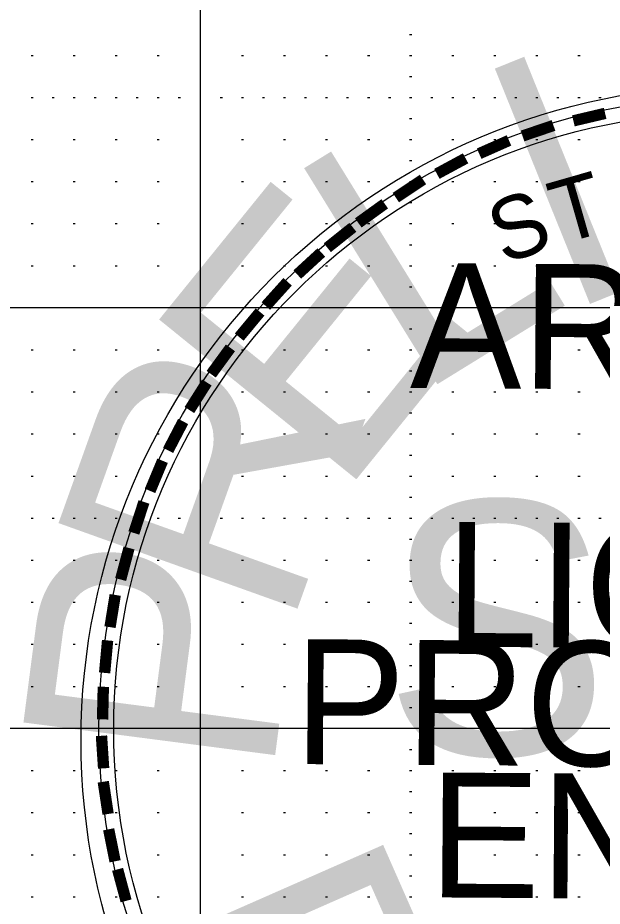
# Model space of a CAD drawing. Extents: x -1.6 to 32.4, y -1.9 to 21.6.
# Drawn here: x 27.374 to 28.763, y 17.122 to 19.234 of the extents above; entities that cross this region are included whole.
import ezdxf

# ---------------------------------------------------------------- set-up
doc = ezdxf.new("R2010")
doc.units = 0
for name, color, linetype in [('Level 4', 7, 'Continuous'), ('Level 49', 7, 'Continuous'), ('Level 5', 7, 'Continuous'), ('R_Border Prelim', 7, 'Continuous'), ('Stamp Mask', 7, 'Continuous')]:
    doc.layers.add(name, color=color, linetype=linetype)

msp = doc.modelspace()

# ---------------------------------------------------------------- linework, layer by layer
at = {"layer": 'Level 4'}
for p, q in [((27.808, 0.545), (27.808, 19.7217)), ((31.617, 18.545), (-0.001, 18.545)), ((31.617, 17.545), (-0.001, 17.545))]:
    msp.add_line(p, q, dxfattribs=at)
at = {"layer": 'Level 5'}
for p, q in [((28.3055, 19.195), (28.3105, 19.195)), ((27.4055, 19.145), (27.4105, 19.145)), ((27.5055, 19.145), (27.5105, 19.145)), ((27.6055, 19.145), (27.6105, 19.145)), ((27.7055, 19.145), (27.7105, 19.145)), ((27.9055, 19.145), (27.9105, 19.145)), ((28.0055, 19.145), (28.0105, 19.145)), ((28.1055, 19.145), (28.1105, 19.145)), ((28.2055, 19.145), (28.2105, 19.145)), ((28.3055, 19.145), (28.3105, 19.145)), ((28.4055, 19.145), (28.4105, 19.145)), ((28.5055, 19.145), (28.5105, 19.145)), ((28.6055, 19.145), (28.6105, 19.145)), ((28.7055, 19.145), (28.7105, 19.145)), ((28.3055, 19.095), (28.3105, 19.095)), ((27.4055, 19.045), (27.4105, 19.045)), ((27.4555, 19.045), (27.4605, 19.045)), ((27.5055, 19.045), (27.5105, 19.045)), ((27.5555, 19.045), (27.5605, 19.045)), ((27.6055, 19.045), (27.6105, 19.045)), ((27.6555, 19.045), (27.6605, 19.045)), ((27.7055, 19.045), (27.7105, 19.045)), ((27.7555, 19.045), (27.7605, 19.045)), ((27.8555, 19.045), (27.8605, 19.045)), ((27.9055, 19.045), (27.9105, 19.045)), ((27.9555, 19.045), (27.9605, 19.045)), ((28.0055, 19.045), (28.0105, 19.045)), ((28.0555, 19.045), (28.0605, 19.045)), ((28.1055, 19.045), (28.1105, 19.045)), ((28.1555, 19.045), (28.1605, 19.045)), ((28.2055, 19.045), (28.2105, 19.045)), ((28.2555, 19.045), (28.2605, 19.045)), ((28.3055, 19.045), (28.3105, 19.045)), ((28.3555, 19.045), (28.3605, 19.045)), ((28.4055, 19.045), (28.4105, 19.045)), ((28.4555, 19.045), (28.4605, 19.045)), ((28.5055, 19.045), (28.5105, 19.045)), ((28.5555, 19.045), (28.5605, 19.045)), ((28.6055, 19.045), (28.6105, 19.045)), ((28.6555, 19.045), (28.6605, 19.045)), ((28.7055, 19.045), (28.7105, 19.045)), ((28.7555, 19.045), (28.7605, 19.045)), ((28.3055, 18.995), (28.3105, 18.995)), ((27.4055, 18.945), (27.4105, 18.945)), ((27.5055, 18.945), (27.5105, 18.945)), ((27.6055, 18.945), (27.6105, 18.945)), ((27.7055, 18.945), (27.7105, 18.945)), ((27.9055, 18.945), (27.9105, 18.945)), ((28.0055, 18.945), (28.0105, 18.945)), ((28.1055, 18.945), (28.1105, 18.945)), ((28.2055, 18.945), (28.2105, 18.945)), ((28.3055, 18.945), (28.3105, 18.945)), ((28.4055, 18.945), (28.4105, 18.945)), ((28.5055, 18.945), (28.5105, 18.945)), ((28.6055, 18.945), (28.6105, 18.945)), ((28.7055, 18.945), (28.7105, 18.945)), ((28.3055, 18.895), (28.3105, 18.895)), ((27.4055, 18.845), (27.4105, 18.845)), ((27.5055, 18.845), (27.5105, 18.845)), ((27.6055, 18.845), (27.6105, 18.845)), ((27.7055, 18.845), (27.7105, 18.845)), ((27.9055, 18.845), (27.9105, 18.845)), ((28.0055, 18.845), (28.0105, 18.845)), ((28.1055, 18.845), (28.1105, 18.845)), ((28.2055, 18.845), (28.2105, 18.845)), ((28.3055, 18.845), (28.3105, 18.845)), ((28.4055, 18.845), (28.4105, 18.845)), ((28.5055, 18.845), (28.5105, 18.845)), ((28.6055, 18.845), (28.6105, 18.845)), ((28.7055, 18.845), (28.7105, 18.845)), ((28.3055, 18.795), (28.3105, 18.795)), ((27.4055, 18.745), (27.4105, 18.745)), ((27.5055, 18.745), (27.5105, 18.745)), ((27.6055, 18.745), (27.6105, 18.745)), ((27.7055, 18.745), (27.7105, 18.745)), ((27.9055, 18.745), (27.9105, 18.745)), ((28.0055, 18.745), (28.0105, 18.745)), ((28.1055, 18.745), (28.1105, 18.745)), ((28.2055, 18.745), (28.2105, 18.745)), ((28.3055, 18.745), (28.3105, 18.745)), ((28.4055, 18.745), (28.4105, 18.745)), ((28.5055, 18.745), (28.5105, 18.745)), ((28.6055, 18.745), (28.6105, 18.745)), ((28.7055, 18.745), (28.7105, 18.745)), ((28.3055, 18.695), (28.3105, 18.695)), ((27.4055, 18.645), (27.4105, 18.645)), ((27.5055, 18.645), (27.5105, 18.645)), ((27.6055, 18.645), (27.6105, 18.645)), ((27.7055, 18.645), (27.7105, 18.645)), ((27.9055, 18.645), (27.9105, 18.645)), ((28.0055, 18.645), (28.0105, 18.645)), ((28.1055, 18.645), (28.1105, 18.645)), ((28.2055, 18.645), (28.2105, 18.645)), ((28.3055, 18.645), (28.3105, 18.645)), ((28.4055, 18.645), (28.4105, 18.645)), ((28.5055, 18.645), (28.5105, 18.645)), ((28.6055, 18.645), (28.6105, 18.645)), ((28.7055, 18.645), (28.7105, 18.645)), ((28.3055, 18.595), (28.3105, 18.595)), ((28.3055, 18.495), (28.3105, 18.495)), ((27.4055, 18.445), (27.4105, 18.445)), ((27.5055, 18.445), (27.5105, 18.445)), ((27.6055, 18.445), (27.6105, 18.445)), ((27.7055, 18.445), (27.7105, 18.445)), ((27.9055, 18.445), (27.9105, 18.445)), ((28.0055, 18.445), (28.0105, 18.445)), ((28.1055, 18.445), (28.1105, 18.445)), ((28.2055, 18.445), (28.2105, 18.445)), ((28.3055, 18.445), (28.3105, 18.445)), ((28.4055, 18.445), (28.4105, 18.445)), ((28.5055, 18.445), (28.5105, 18.445)), ((28.6055, 18.445), (28.6105, 18.445)), ((28.7055, 18.445), (28.7105, 18.445)), ((28.3055, 18.395), (28.3105, 18.395)), ((27.4055, 18.345), (27.4105, 18.345)), ((27.5055, 18.345), (27.5105, 18.345)), ((27.6055, 18.345), (27.6105, 18.345)), ((27.7055, 18.345), (27.7105, 18.345)), ((27.9055, 18.345), (27.9105, 18.345)), ((28.0055, 18.345), (28.0105, 18.345)), ((28.1055, 18.345), (28.1105, 18.345)), ((28.2055, 18.345), (28.2105, 18.345)), ((28.3055, 18.345), (28.3105, 18.345)), ((28.4055, 18.345), (28.4105, 18.345)), ((28.5055, 18.345), (28.5105, 18.345)), ((28.6055, 18.345), (28.6105, 18.345)), ((28.7055, 18.345), (28.7105, 18.345)), ((28.3055, 18.295), (28.3105, 18.295)), ((27.4055, 18.245), (27.4105, 18.245)), ((27.5055, 18.245), (27.5105, 18.245)), ((27.6055, 18.245), (27.6105, 18.245)), ((27.7055, 18.245), (27.7105, 18.245)), ((27.9055, 18.245), (27.9105, 18.245)), ((28.0055, 18.245), (28.0105, 18.245)), ((28.1055, 18.245), (28.1105, 18.245)), ((28.2055, 18.245), (28.2105, 18.245)), ((28.3055, 18.245), (28.3105, 18.245)), ((28.4055, 18.245), (28.4105, 18.245)), ((28.5055, 18.245), (28.5105, 18.245)), ((28.6055, 18.245), (28.6105, 18.245)), ((28.7055, 18.245), (28.7105, 18.245)), ((28.3055, 18.195), (28.3105, 18.195)), ((27.4055, 18.145), (27.4105, 18.145)), ((27.5055, 18.145), (27.5105, 18.145)), ((27.6055, 18.145), (27.6105, 18.145)), ((27.7055, 18.145), (27.7105, 18.145)), ((27.9055, 18.145), (27.9105, 18.145)), ((28.0055, 18.145), (28.0105, 18.145)), ((28.1055, 18.145), (28.1105, 18.145)), ((28.2055, 18.145), (28.2105, 18.145)), ((28.3055, 18.145), (28.3105, 18.145)), ((28.4055, 18.145), (28.4105, 18.145)), ((28.5055, 18.145), (28.5105, 18.145)), ((28.6055, 18.145), (28.6105, 18.145)), ((28.7055, 18.145), (28.7105, 18.145)), ((28.3055, 18.095), (28.3105, 18.095)), ((27.4055, 18.045), (27.4105, 18.045)), ((27.4555, 18.045), (27.4605, 18.045)), ((27.5055, 18.045), (27.5105, 18.045)), ((27.5555, 18.045), (27.5605, 18.045)), ((27.6055, 18.045), (27.6105, 18.045)), ((27.6555, 18.045), (27.6605, 18.045)), ((27.7055, 18.045), (27.7105, 18.045)), ((27.7555, 18.045), (27.7605, 18.045)), ((27.8555, 18.045), (27.8605, 18.045)), ((27.9055, 18.045), (27.9105, 18.045)), ((27.9555, 18.045), (27.9605, 18.045)), ((28.0055, 18.045), (28.0105, 18.045)), ((28.0555, 18.045), (28.0605, 18.045)), ((28.1055, 18.045), (28.1105, 18.045)), ((28.1555, 18.045), (28.1605, 18.045)), ((28.2055, 18.045), (28.2105, 18.045)), ((28.2555, 18.045), (28.2605, 18.045)), ((28.3055, 18.045), (28.3105, 18.045)), ((28.3555, 18.045), (28.3605, 18.045)), ((28.4055, 18.045), (28.4105, 18.045)), ((28.4555, 18.045), (28.4605, 18.045)), ((28.5055, 18.045), (28.5105, 18.045)), ((28.5555, 18.045), (28.5605, 18.045)), ((28.6055, 18.045), (28.6105, 18.045)), ((28.6555, 18.045), (28.6605, 18.045)), ((28.7055, 18.045), (28.7105, 18.045)), ((28.7555, 18.045), (28.7605, 18.045)), ((28.3055, 17.995), (28.3105, 17.995)), ((27.4055, 17.945), (27.4105, 17.945)), ((27.5055, 17.945), (27.5105, 17.945)), ((27.6055, 17.945), (27.6105, 17.945)), ((27.7055, 17.945), (27.7105, 17.945)), ((27.9055, 17.945), (27.9105, 17.945)), ((28.0055, 17.945), (28.0105, 17.945)), ((28.1055, 17.945), (28.1105, 17.945)), ((28.2055, 17.945), (28.2105, 17.945)), ((28.3055, 17.945), (28.3105, 17.945)), ((28.4055, 17.945), (28.4105, 17.945)), ((28.5055, 17.945), (28.5105, 17.945)), ((28.6055, 17.945), (28.6105, 17.945)), ((28.7055, 17.945), (28.7105, 17.945)), ((28.3055, 17.895), (28.3105, 17.895)), ((27.4055, 17.845), (27.4105, 17.845)), ((27.5055, 17.845), (27.5105, 17.845)), ((27.6055, 17.845), (27.6105, 17.845)), ((27.7055, 17.845), (27.7105, 17.845)), ((27.9055, 17.845), (27.9105, 17.845)), ((28.0055, 17.845), (28.0105, 17.845)), ((28.1055, 17.845), (28.1105, 17.845)), ((28.2055, 17.845), (28.2105, 17.845)), ((28.3055, 17.845), (28.3105, 17.845)), ((28.4055, 17.845), (28.4105, 17.845)), ((28.5055, 17.845), (28.5105, 17.845)), ((28.6055, 17.845), (28.6105, 17.845)), ((28.7055, 17.845), (28.7105, 17.845)), ((28.3055, 17.795), (28.3105, 17.795)), ((27.4055, 17.745), (27.4105, 17.745)), ((27.5055, 17.745), (27.5105, 17.745)), ((27.6055, 17.745), (27.6105, 17.745)), ((27.7055, 17.745), (27.7105, 17.745)), ((27.9055, 17.745), (27.9105, 17.745)), ((28.0055, 17.745), (28.0105, 17.745)), ((28.1055, 17.745), (28.1105, 17.745)), ((28.2055, 17.745), (28.2105, 17.745)), ((28.3055, 17.745), (28.3105, 17.745)), ((28.4055, 17.745), (28.4105, 17.745)), ((28.5055, 17.745), (28.5105, 17.745)), ((28.6055, 17.745), (28.6105, 17.745)), ((28.7055, 17.745), (28.7105, 17.745)), ((28.3055, 17.695), (28.3105, 17.695)), ((27.4055, 17.645), (27.4105, 17.645)), ((27.5055, 17.645), (27.5105, 17.645)), ((27.6055, 17.645), (27.6105, 17.645)), ((27.7055, 17.645), (27.7105, 17.645)), ((27.9055, 17.645), (27.9105, 17.645)), ((28.0055, 17.645), (28.0105, 17.645)), ((28.1055, 17.645), (28.1105, 17.645)), ((28.2055, 17.645), (28.2105, 17.645)), ((28.3055, 17.645), (28.3105, 17.645)), ((28.4055, 17.645), (28.4105, 17.645)), ((28.5055, 17.645), (28.5105, 17.645)), ((28.6055, 17.645), (28.6105, 17.645)), ((28.7055, 17.645), (28.7105, 17.645)), ((28.3055, 17.595), (28.3105, 17.595)), ((28.3055, 17.495), (28.3105, 17.495)), ((27.4055, 17.445), (27.4105, 17.445)), ((27.5055, 17.445), (27.5105, 17.445)), ((27.6055, 17.445), (27.6105, 17.445)), ((27.7055, 17.445), (27.7105, 17.445)), ((27.9055, 17.445), (27.9105, 17.445)), ((28.0055, 17.445), (28.0105, 17.445)), ((28.1055, 17.445), (28.1105, 17.445)), ((28.2055, 17.445), (28.2105, 17.445)), ((28.3055, 17.445), (28.3105, 17.445)), ((28.4055, 17.445), (28.4105, 17.445)), ((28.5055, 17.445), (28.5105, 17.445)), ((28.6055, 17.445), (28.6105, 17.445)), ((28.7055, 17.445), (28.7105, 17.445)), ((28.3055, 17.395), (28.3105, 17.395)), ((27.4055, 17.345), (27.4105, 17.345)), ((27.5055, 17.345), (27.5105, 17.345)), ((27.6055, 17.345), (27.6105, 17.345)), ((27.7055, 17.345), (27.7105, 17.345)), ((27.9055, 17.345), (27.9105, 17.345)), ((28.0055, 17.345), (28.0105, 17.345)), ((28.1055, 17.345), (28.1105, 17.345)), ((28.2055, 17.345), (28.2105, 17.345)), ((28.3055, 17.345), (28.3105, 17.345)), ((28.4055, 17.345), (28.4105, 17.345)), ((28.5055, 17.345), (28.5105, 17.345)), ((28.6055, 17.345), (28.6105, 17.345)), ((28.7055, 17.345), (28.7105, 17.345)), ((28.3055, 17.295), (28.3105, 17.295)), ((27.4055, 17.245), (27.4105, 17.245)), ((27.5055, 17.245), (27.5105, 17.245)), ((27.6055, 17.245), (27.6105, 17.245)), ((27.7055, 17.245), (27.7105, 17.245)), ((27.9055, 17.245), (27.9105, 17.245)), ((28.0055, 17.245), (28.0105, 17.245)), ((28.1055, 17.245), (28.1105, 17.245)), ((28.2055, 17.245), (28.2105, 17.245)), ((28.3055, 17.245), (28.3105, 17.245)), ((28.4055, 17.245), (28.4105, 17.245)), ((28.5055, 17.245), (28.5105, 17.245)), ((28.6055, 17.245), (28.6105, 17.245)), ((28.7055, 17.245), (28.7105, 17.245)), ((28.3055, 17.195), (28.3105, 17.195)), ((27.4055, 17.145), (27.4105, 17.145)), ((27.5055, 17.145), (27.5105, 17.145)), ((27.6055, 17.145), (27.6105, 17.145)), ((27.7055, 17.145), (27.7105, 17.145)), ((27.9055, 17.145), (27.9105, 17.145)), ((28.0055, 17.145), (28.0105, 17.145)), ((28.1055, 17.145), (28.1105, 17.145)), ((28.2055, 17.145), (28.2105, 17.145)), ((28.3055, 17.145), (28.3105, 17.145)), ((28.4055, 17.145), (28.4105, 17.145)), ((28.5055, 17.145), (28.5105, 17.145)), ((28.6055, 17.145), (28.6105, 17.145)), ((28.7055, 17.145), (28.7105, 17.145))]:
    msp.add_line(p, q, dxfattribs=at)
at = {"layer": 'R_Border Prelim'}
msp.add_circle((29.0672, 17.545), 1.5001, dxfattribs=at)
at = {"layer": 'Stamp Mask'}
for centre, radius in [((29.0813, 17.5168), 1.5568), ((29.0679, 17.5442), 1.4658)]:
    msp.add_circle(centre, radius, dxfattribs=at)

# ---------------------------------------------------------------- texts
at = {"layer": 'Level 49'}
for s, height, rotation, p in [('-', 0.2374, 13.2326, (28.702, 18.8969)), ('-', 0.2374, 18.7785, (28.5902, 18.8621)), ('-', 0.2375, 23.9096, (28.495, 18.8218)), ('-', 0.2375, 28.3942, (28.4015, 18.776)), ('-', 0.2375, 33.666, (28.3118, 18.7228)), ('T', 0.1484, 16.006, (28.6654, 18.6953)), ('S', 0.1484, 21.1964, (28.5298, 18.6459)), ('-', 0.2374, 35.8341, (28.2257, 18.6642)), ('-', 0.2374, 38.5531, (28.156, 18.6074)), ('-', 0.2374, 42.5646, (28.0901, 18.547)), ('ARKANSAS', 0.29686, 359.6024, (28.3063, 18.3546)), ('-', 0.2375, 48.0254, (28.0223, 18.4773)), ('-', 0.2374, 50.2166, (27.9618, 18.4059)), ('-', 0.2375, 53.8349, (27.8995, 18.3216)), ('-', 0.2375, 57.673, (27.8519, 18.241)), ('-', 0.2374, 62.4738, (27.8061, 18.1512)), ('-', 0.2374, 67.3767, (27.7676, 18.0615)), ('-', 0.2374, 71.9969, (27.7328, 17.968)), ('LICENSED', 0.29686, 359.6024, (28.3893, 17.7395)), ('-', 0.2375, 75.0634, (27.7035, 17.8618)), ('-', 0.2374, 80.8037, (27.6815, 17.7573)), ('-', 0.2374, 84.7887, (27.6705, 17.6547)), ('PROFESSIONAL', 0.296862, 359.6024, (28.0296, 17.4605)), ('-', 0.2375, 88.6646, (27.6669, 17.5503)), ('-', 0.2374, 93.7983, (27.6705, 17.4422)), ('ENGINEER', 0.29686, 359.6024, (28.3502, 17.1436)), ('-', 0.2374, 98.5503, (27.6815, 17.3414)), ('-', 0.2375, 101.3173, (27.698, 17.2334)), ('-', 0.2375, 105.0602, (27.7237, 17.1454))]:
    msp.add_text(s, height=height, rotation=rotation, dxfattribs=at).set_placement(p)
at = {"layer": 'R_Border Prelim'}
for s, rotation, p in [('I', 22.0105, (28.6652, 18.5262)), ('L', 31.6686, (28.3152, 18.3286)), ('E', 50.9849, (28.1372, 18.0858)), ('R', 70.3011, (28.0166, 17.7675)), ('P', 82.6089, (27.9774, 17.416)), ('R', 293.7639, (27.6636, 17.0857))]:
    msp.add_text(s, height=0.6034, rotation=rotation, dxfattribs=at).set_placement(p)
msp.add_text('SUBJECT', height=0.60336, dxfattribs=at).set_placement((28.2428, 17.4824))

doc.saveas('drawing.dxf')
